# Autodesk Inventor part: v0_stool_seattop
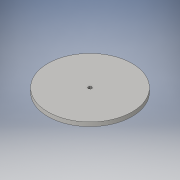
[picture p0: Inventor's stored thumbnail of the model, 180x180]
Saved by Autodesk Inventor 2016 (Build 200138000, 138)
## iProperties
Created: 2015-07
Part Number: v0_stool_seattop
Material: Generic
Document SubType Name: Modeling
Designer: t_patrw
Density: 1 g/cm^3
Appearance: Default
Author: t_patrw
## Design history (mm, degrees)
sketch "Sketch1"
  geometry: C1 r 190.5 at (0, 0); 1 further point
  constraints: 1 centre point, 1 coincident
  dimensions: "d0" = 381 diameter of C1 (= Seat_Diameter)
extrude "Extrusion1" new body sketch "Sketch1" distance "d1" = 18.288 (= Thickness); taper "d2" = 0 deg
sketch "Sketch2"
  geometry: L1 (0, 8.212)-(7.112, 4.106); L2 (7.112, 4.106)-(7.112, -4.106); L3 (7.112, -4.106)-(0, -8.212); L4 (0, -8.212)-(-7.112, -4.106); L5 (-7.112, -4.106)-(-7.112, 4.106); L6 (-7.112, 4.106)-(0, 8.212); 2 further points
  constraints: 12 end point, 1 coincident, 13 other
  dimensions: "d3" = 14.224 distance between parallel lines of L2 L5
extrude "Extrusion2" cut sketch "Sketch2" distance "d4" = 18.288 (= Thickness); taper "d5" = 0 deg
body "Solid1"
other parameters: "Thickness" = 18.288 [user parameter; used in 2 equation terms], "Height" = 457.2 [user parameter], "Seat_Diameter" = 381 [user parameter; used in 1 equation term]
